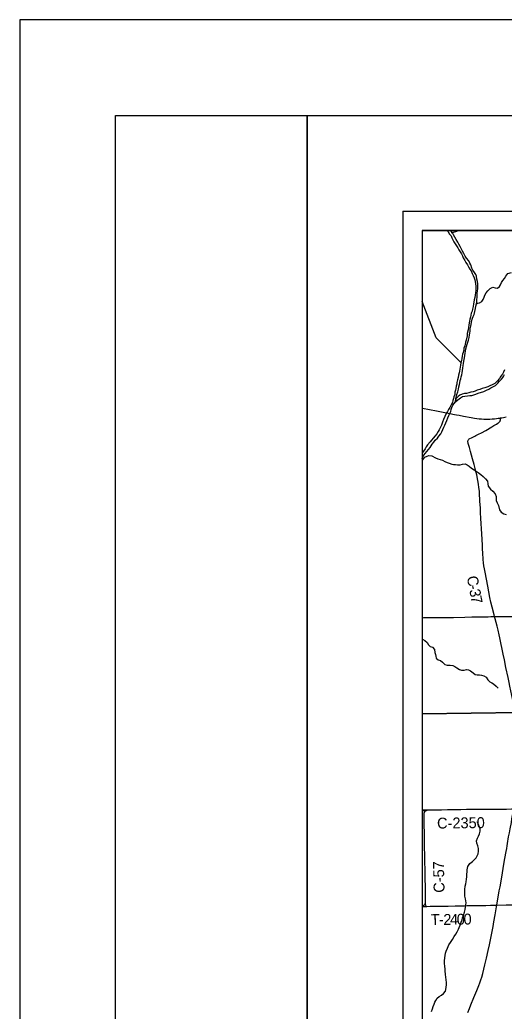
# Model space of a CAD drawing. Extents: x 0 to 34, y 0 to 22.
# Drawn here: x 0 to 2.53, y 16.82 to 22 of the extents above; entities that cross this region are included whole.
import ezdxf

# ---------------------------------------------------------------- set-up
doc = ezdxf.new("R2010")
doc.units = 0
for name, color, linetype in [('Default', 7, 'Continuous'), ('GM_X_County_Road', 7, 'Continuous'), ('GM_X_County_Road_Text', 7, 'Continuous'), ('GM_X_Major_River', 7, 'Continuous'), ('GM_X_Minor_River', 7, 'Continuous'), ('GM_X_State_Route', 7, 'Continuous'), ('GM_X_Township_Road', 7, 'Continuous'), ('GM_X_Township_Road_Text', 7, 'Continuous'), ('SH_Border', 7, 'Continuous'), ('SH_Cut_Line', 7, 'Continuous'), ('SH_Data', 7, 'Continuous')]:
    doc.layers.add(name, color=color, linetype=linetype)

msp = doc.modelspace()

# ---------------------------------------------------------------- linework, layer by layer
at = {"layer": 'Default'}
for points in [[(2.6032, 20.9), (2.1, 20.9), (2.1, 18.375), (2.6118, 18.3803), (2.6161, 18.3799), (2.6204, 18.3797), (2.6263, 18.3795), (2.6292, 18.3794), (2.6281, 18.8843), (2.6224, 19.9515), (2.6032, 20.8721)], [(2.1, 18.375), (2.1, 14.3539), (2.1651, 14.3567), (2.6607, 14.3625), (2.6434, 15.3487), (2.6428, 15.3713), (2.6388, 15.4856), (2.6332, 16.3685), (2.6231, 17.3771), (2.6129, 17.8818), (2.6122, 18.05), (2.6118, 18.3803)]]:
    msp.add_lwpolyline(points, close=True, dxfattribs=at)
at = {"layer": 'GM_X_County_Road'}
for points in [[(2.4785, 18.8823), (2.476, 18.8918), (2.4659, 18.931), (2.4594, 18.9582), (2.4543, 18.9825), (2.443, 19.0404), (2.4287, 19.1136), (2.4252, 19.1319), (2.4228, 19.1473), (2.421, 19.1628), (2.4195, 19.1813), (2.4173, 19.2153), (2.4162, 19.2339), (2.4148, 19.2556), (2.4114, 19.3146), (2.407, 19.3952), (2.4054, 19.4262), (2.4043, 19.448), (2.4024, 19.4851), (2.3998, 19.5284), (2.399, 19.5376), (2.3972, 19.5561), (2.3946, 19.5746), (2.3915, 19.5929), (2.3897, 19.6021), (2.3872, 19.6141), (2.3852, 19.6231), (2.3808, 19.6407), (2.3793, 19.6466), (2.377, 19.6556), (2.3714, 19.6766), (2.3631, 19.7065), (2.3527, 19.7455), (2.347, 19.7663), (2.3427, 19.7812), (2.341, 19.7873), (2.3403, 19.7903), (2.3397, 19.7936), (2.3394, 19.7969), (2.3397, 19.8005), (2.3404, 19.8034), (2.342, 19.8063), (2.3442, 19.8086), (2.3465, 19.8107), (2.3493, 19.8124), (2.358, 19.8164), (2.3747, 19.8246), (2.3802, 19.8275), (2.3941, 19.8344), (2.4105, 19.8431), (2.4322, 19.8552), (2.4644, 19.8736), (2.4751, 19.8798), (2.4858, 19.8862), (2.4885, 19.8877), (2.4963, 19.8927), (2.4988, 19.8945), (2.5011, 19.8965), (2.5033, 19.8985), (2.5052, 19.9007), (2.5069, 19.9032), (2.5081, 19.9058), (2.5089, 19.9086), (2.5092, 19.9115), (2.51, 19.92)], [(2.612, 18.3797), (2.605, 18.3816), (2.6008, 18.3837), (2.5961, 18.3866), (2.5918, 18.3897), (2.5882, 18.3934), (2.5844, 18.3998), (2.5827, 18.4047), (2.5816, 18.4095), (2.5789, 18.4216), (2.5635, 18.4945), (2.5585, 18.5189), (2.5548, 18.5371), (2.5491, 18.5645), (2.5379, 18.6161), (2.5297, 18.6557), (2.5233, 18.6861), (2.5056, 18.7712), (2.5023, 18.7864), (2.4967, 18.8106), (2.4913, 18.8316), (2.4814, 18.8708), (2.4785, 18.8823)], [(2.113, 17.8603), (2.1148, 17.8631), (2.1167, 17.865), (2.1199, 17.8677), (2.1232, 17.8697), (2.1271, 17.8713), (2.1302, 17.8721), (2.1338, 17.8727)], [(2.1338, 17.8727), (2.143, 17.873), (2.1679, 17.8731), (2.2021, 17.8734), (2.2332, 17.8737), (2.2706, 17.8742), (2.3017, 17.8749), (2.3328, 17.8752), (2.3483, 17.8753), (2.3639, 17.8754), (2.3825, 17.8755), (2.4074, 17.8755), (2.4447, 17.8757), (2.4883, 17.8761), (2.5256, 17.8767), (2.5411, 17.8769), (2.5661, 17.877), (2.5714, 17.8773), (2.5741, 17.8774), (2.5755, 17.8776), (2.5786, 17.8784), (2.5792, 17.8787)], [(2.4906, 17.3748), (2.5032, 17.4493), (2.507, 17.4707), (2.5177, 17.5319), (2.5258, 17.5778), (2.5327, 17.6176), (2.5393, 17.6543), (2.5418, 17.6697), (2.5441, 17.685), (2.546, 17.6973), (2.5521, 17.7309), (2.5561, 17.7522), (2.5601, 17.7736), (2.5662, 17.8072), (2.5695, 17.8255), (2.5792, 17.8787)], [(2.1156, 17.3812), (2.1165, 17.3836), (2.1171, 17.3856), (2.1176, 17.3877), (2.1179, 17.3899), (2.1182, 17.3935), (2.1187, 17.4028), (2.1187, 17.4277), (2.1178, 17.4682), (2.1168, 17.5149), (2.116, 17.5616), (2.1152, 17.599), (2.1145, 17.627), (2.1133, 17.6862), (2.1125, 17.736), (2.1105, 17.8077), (2.1102, 17.8214), (2.1105, 17.8354), (2.1105, 17.8414), (2.1107, 17.8482), (2.111, 17.8518), (2.1116, 17.8556), (2.113, 17.8603)], [(2.1, 17.3692), (2.1009, 17.3694), (2.1042, 17.3705), (2.1075, 17.3721), (2.1099, 17.3737), (2.1125, 17.3761), (2.1143, 17.3787), (2.1156, 17.3812)], [(2.3387, 16.8142), (2.347, 16.8343), (2.3551, 16.8545), (2.37, 16.8919), (2.3858, 16.9289), (2.3965, 16.9546), (2.4022, 16.9691), (2.4073, 16.9838), (2.4119, 16.9987), (2.4168, 17.0167), (2.4277, 17.062), (2.4362, 17.0983), (2.4451, 17.1377), (2.4516, 17.1681), (2.4623, 17.2199), (2.4708, 17.2625), (2.4753, 17.287), (2.4817, 17.3237), (2.4892, 17.3666), (2.4906, 17.3748)]]:
    msp.add_lwpolyline(points, dxfattribs=at)
at = {"layer": 'GM_X_Major_River'}
for points in [[(2.2303, 20.9), (2.236, 20.892), (2.2439, 20.8809), (2.2511, 20.8714), (2.2548, 20.8604), (2.2605, 20.8505)], [(2.3133, 20.1805), (2.3151, 20.1946), (2.3163, 20.2048), (2.3177, 20.217), (2.3207, 20.2333), (2.3226, 20.2466), (2.3244, 20.258), (2.3263, 20.2697), (2.3293, 20.2807), (2.3323, 20.294), (2.3357, 20.3047), (2.3395, 20.3157), (2.3425, 20.3267), (2.3454, 20.34), (2.3484, 20.3536), (2.3496, 20.3631), (2.3503, 20.373), (2.3518, 20.3851), (2.3548, 20.3992), (2.3562, 20.4087), (2.3589, 20.4204), (2.3622, 20.436), (2.3667, 20.4493), (2.3713, 20.4603), (2.3754, 20.4759), (2.3784, 20.4911), (2.3814, 20.5036), (2.3836, 20.5154), (2.3855, 20.5256), (2.3866, 20.5389), (2.3869, 20.5499), (2.3873, 20.5617), (2.388, 20.5715), (2.3895, 20.5837), (2.391, 20.5954), (2.3917, 20.608), (2.3905, 20.6209), (2.389, 20.6322), (2.3867, 20.6459), (2.3836, 20.6599), (2.3801, 20.6694), (2.3737, 20.68), (2.3649, 20.6925), (2.3599, 20.7023), (2.3538, 20.7194), (2.35, 20.7292), (2.3435, 20.7417), (2.3317, 20.7554), (2.3249, 20.7656), (2.3176, 20.7785), (2.3111, 20.791), (2.3058, 20.8023), (2.2985, 20.8164), (2.2924, 20.8281), (2.286, 20.8379), (2.2787, 20.852), (2.2711, 20.8645), (2.2646, 20.8762), (2.2585, 20.8864), (2.252, 20.8966), (2.2504, 20.9)], [(2.2605, 20.8505), (2.2657, 20.8406), (2.2733, 20.8299), (2.2796, 20.8192), (2.2864, 20.8086), (2.2924, 20.7983), (2.2981, 20.7876), (2.3052, 20.7766), (2.3108, 20.7671), (2.3153, 20.7572), (2.3232, 20.7427), (2.3288, 20.7317), (2.3364, 20.7206), (2.342, 20.7092), (2.3495, 20.6978), (2.3567, 20.6879), (2.3615, 20.6742), (2.3672, 20.6635), (2.372, 20.6529), (2.3746, 20.6422), (2.378, 20.6323), (2.3794, 20.6206), (2.3801, 20.608), (2.3805, 20.5978), (2.38, 20.5853), (2.3784, 20.5747), (2.3776, 20.5614), (2.3753, 20.5489), (2.3722, 20.5371), (2.3706, 20.5254), (2.3686, 20.5159), (2.3667, 20.5026), (2.3632, 20.4882), (2.3609, 20.4787), (2.357, 20.4678), (2.3551, 20.4572), (2.3524, 20.4465), (2.35, 20.4367), (2.3481, 20.4265), (2.3458, 20.4166), (2.3442, 20.4048), (2.3418, 20.392), (2.3403, 20.3806), (2.3348, 20.3605), (2.3348, 20.3491), (2.3309, 20.3271), (2.3266, 20.3158), (2.3254, 20.3059), (2.3231, 20.2961), (2.3185, 20.2843), (2.3181, 20.2748), (2.3146, 20.2627), (2.3119, 20.2525), (2.3099, 20.2422), (2.308, 20.2309), (2.3057, 20.2195), (2.3022, 20.2074), (2.3002, 20.1964), (2.2986, 20.1846), (2.2967, 20.1748), (2.2951, 20.1645), (2.2932, 20.1551), (2.2897, 20.1437), (2.2877, 20.1312), (2.2846, 20.1187), (2.2823, 20.1054), (2.2811, 20.0959), (2.2773, 20.0853), (2.2757, 20.0743), (2.2753, 20.0645), (2.2714, 20.0542), (2.2714, 20.0429), (2.266, 20.0311), (2.2644, 20.0209), (2.2613, 20.011), (2.2586, 20.0009)], [(2.2762, 20.0203), (2.2811, 20.0423), (2.2867, 20.056), (2.2901, 20.0697), (2.2927, 20.0822), (2.2946, 20.0943), (2.2968, 20.1042), (2.2994, 20.1148), (2.3021, 20.1243), (2.3047, 20.135), (2.3069, 20.1445), (2.3092, 20.1551), (2.3114, 20.168), (2.3133, 20.1805)], [(2.1, 19.7082), (2.1063, 19.7203), (2.1168, 19.7347), (2.1244, 19.7443), (2.133, 19.7549), (2.1417, 19.7663), (2.1534, 19.7831), (2.1613, 19.7941), (2.1692, 19.8036), (2.1802, 19.8147), (2.1881, 19.825), (2.1971, 19.8364), (2.2035, 19.8474), (2.2088, 19.8596), (2.214, 19.8713), (2.2197, 19.8831), (2.2242, 19.8953), (2.229, 19.9063), (2.235, 19.9208), (2.2399, 19.9322), (2.2448, 19.9424), (2.2497, 19.9531), (2.2527, 19.9633), (2.2553, 19.974), (2.2605, 19.9869), (2.2744, 20.0044)], [(2.2586, 20.0009), (2.2526, 19.9884), (2.2443, 19.9747), (2.2379, 19.9633), (2.2322, 19.9534), (2.2236, 19.9405), (2.2183, 19.9275), (2.2123, 19.9127), (2.2071, 19.8986), (2.2011, 19.8831), (2.1955, 19.8717), (2.1887, 19.8583), (2.1834, 19.8485), (2.1766, 19.8374), (2.1691, 19.8272), (2.1585, 19.8146), (2.1499, 19.8047), (2.1416, 19.7952), (2.1291, 19.7788), (2.122, 19.7689), (2.1167, 19.759), (2.1077, 19.7465), (2.1, 19.7339)], [(2.2744, 20.0044), (2.2762, 20.0203)]]:
    msp.add_lwpolyline(points, dxfattribs=at)
at = {"layer": 'GM_X_Minor_River'}
for points in [[(2.2564, 20.8897), (2.254, 20.8875), (2.2642, 20.8902), (2.2771, 20.8948), (2.2909, 20.9)], [(2.3836, 20.5154), (2.3901, 20.5192), (2.3999, 20.5207), (2.4128, 20.528), (2.4188, 20.5382), (2.4241, 20.5512), (2.4275, 20.5622), (2.4347, 20.5743), (2.4434, 20.5846), (2.4555, 20.5964), (2.4695, 20.6036), (2.4812, 20.5999), (2.4945, 20.5984), (2.5047, 20.6064), (2.5096, 20.6163), (2.5149, 20.6277), (2.5221, 20.6376), (2.5308, 20.6494), (2.5376, 20.6615), (2.5478, 20.6752), (2.567, 20.6805)], [(2.3027, 20.2091), (2.174, 20.3379), (2.1, 20.5276)], [(2.531, 20.1721), (2.5243, 20.1584), (2.5194, 20.1481), (2.5118, 20.1375), (2.505, 20.1265), (2.4925, 20.1116), (2.4797, 20.1006), (2.4664, 20.0933), (2.4531, 20.0872), (2.4429, 20.0827), (2.4274, 20.0773), (2.4137, 20.0735), (2.4009, 20.0685), (2.3884, 20.0643), (2.3766, 20.0597), (2.3671, 20.0562), (2.3539, 20.0547), (2.344, 20.0516), (2.3311, 20.0478), (2.3216, 20.0478), (2.3099, 20.0447), (2.2978, 20.0393), (2.2879, 20.0325), (2.2762, 20.0203)], [(2.2744, 20.0044), (2.2865, 20.0154), (2.3008, 20.0257), (2.3114, 20.0322), (2.3224, 20.0345), (2.3372, 20.0357), (2.3494, 20.0365), (2.36, 20.0376), (2.3698, 20.0407), (2.3801, 20.0441), (2.3933, 20.0491), (2.4217, 20.0587), (2.4358, 20.0656), (2.4483, 20.0709), (2.4589, 20.0766), (2.4725, 20.0846), (2.4827, 20.09), (2.4963, 20.1018), (2.5047, 20.1113), (2.516, 20.1246), (2.5243, 20.136), (2.5311, 20.1474)], [(2.2762, 20.0203), (2.2744, 20.0044)], [(2.1, 19.7015), (2.1041, 19.702), (2.115, 19.7154), (2.126, 19.7207), (2.1358, 19.7246), (2.1502, 19.7223), (2.1707, 19.7118), (2.1821, 19.7069), (2.195, 19.7035), (2.206, 19.7002), (2.2189, 19.693), (2.2307, 19.6866), (2.2417, 19.6832), (2.2554, 19.6787), (2.2649, 19.6776), (2.2747, 19.6761), (2.2857, 19.6754), (2.2986, 19.6758), (2.3115, 19.6785), (2.3255, 19.6794), (2.3357, 19.6748), (2.346, 19.6673), (2.3586, 19.6578), (2.3715, 19.6492), (2.3825, 19.6424), (2.3924, 19.6348), (2.4061, 19.6239), (2.4186, 19.6137), (2.4304, 19.6019), (2.4411, 19.5898), (2.4434, 19.5766), (2.4454, 19.5633), (2.4568, 19.5482), (2.469, 19.538), (2.4815, 19.5232), (2.4865, 19.5103), (2.4877, 19.5005), (2.4877, 19.4887), (2.492, 19.4758), (2.4988, 19.4633), (2.5042, 19.4398), (2.5138, 19.4281), (2.5267, 19.4194), (2.5396, 19.4153)], [(2.1, 18.7665), (2.1019, 18.765), (2.1145, 18.7575), (2.1259, 18.7469), (2.1328, 18.734), (2.1423, 18.7261), (2.154, 18.7227), (2.1651, 18.7102), (2.1667, 18.6954), (2.1694, 18.6844), (2.1713, 18.6746), (2.1732, 18.6651), (2.1839, 18.6568), (2.1968, 18.6523), (2.2067, 18.6447), (2.2181, 18.6322), (2.231, 18.6281), (2.2469, 18.6286), (2.2609, 18.6263), (2.2708, 18.6214), (2.2811, 18.615), (2.2959, 18.606), (2.3061, 18.6018), (2.3205, 18.603), (2.3315, 18.605), (2.3418, 18.6046), (2.3524, 18.599), (2.3661, 18.5876), (2.3775, 18.5801), (2.387, 18.5771), (2.3999, 18.5771), (2.4097, 18.5764), (2.423, 18.5723), (2.434, 18.5655), (2.4439, 18.5526), (2.4542, 18.5417), (2.4641, 18.536), (2.4736, 18.5307), (2.4861, 18.5194), (2.4972, 18.5077)], [(2.363, 17.602), (2.3826, 17.6218), (2.3883, 17.6314), (2.392, 17.6431), (2.3954, 17.656), (2.3949, 17.6712), (2.3919, 17.6845), (2.3861, 17.6985), (2.3845, 17.7114), (2.3886, 17.7247), (2.395, 17.7354), (2.3995, 17.7464), (2.4029, 17.7616), (2.4029, 17.7726), (2.3998, 17.7828), (2.3944, 17.7965), (2.3879, 17.8097)], [(2.1484, 16.8191), (2.1536, 16.8331), (2.1577, 16.8445), (2.1626, 16.8574), (2.1667, 16.8673), (2.1716, 16.8772), (2.1784, 16.8879), (2.1886, 16.8978), (2.2015, 16.9043), (2.2113, 16.9123), (2.2218, 16.9245), (2.2241, 16.9343), (2.2263, 16.9461), (2.2278, 16.9586), (2.2277, 16.9689), (2.2261, 16.986), (2.2246, 16.997), (2.2222, 17.0136), (2.221, 17.03), (2.2202, 17.0398), (2.2186, 17.0561), (2.2174, 17.0702), (2.217, 17.0831), (2.2181, 17.099), (2.2199, 17.1112), (2.2225, 17.1241), (2.2259, 17.134), (2.2319, 17.1499), (2.2402, 17.167), (2.2488, 17.1796), (2.259, 17.1959), (2.2676, 17.2112), (2.2759, 17.2226), (2.2831, 17.2355), (2.2895, 17.2484), (2.2936, 17.2579), (2.2985, 17.2701), (2.3045, 17.2864), (2.309, 17.2986), (2.3112, 17.3089), (2.3157, 17.321), (2.3209, 17.3374), (2.3254, 17.351), (2.3273, 17.3632), (2.3291, 17.3761), (2.3294, 17.3863), (2.3279, 17.3973), (2.3263, 17.4068), (2.324, 17.4216), (2.3232, 17.4319), (2.3224, 17.4474), (2.3227, 17.4569), (2.3253, 17.4736), (2.3279, 17.4854), (2.3301, 17.4964), (2.3323, 17.5101), (2.3334, 17.5226), (2.3345, 17.5367), (2.3352, 17.548), (2.3359, 17.5598), (2.3389, 17.5758), (2.3502, 17.5914), (2.363, 17.602)]]:
    msp.add_lwpolyline(points, dxfattribs=at)
at = {"layer": 'GM_X_State_Route'}
msp.add_lwpolyline([(2.1, 19.9721), (2.1024, 19.9716), (2.1757, 19.9576), (2.2275, 19.9473), (2.2458, 19.9437), (2.2701, 19.9388), (2.2792, 19.937), (2.2945, 19.9341), (2.3158, 19.93), (2.3555, 19.9225), (2.3738, 19.9193), (2.3861, 19.9175), (2.3984, 19.9161), (2.4108, 19.9151), (2.4231, 19.9145), (2.4355, 19.9142), (2.4448, 19.9142), (2.4541, 19.9145), (2.4665, 19.9151), (2.4788, 19.9161), (2.4881, 19.917), (2.4973, 19.9181), (2.5065, 19.9195), (2.51, 19.92), (2.5157, 19.921), (2.5248, 19.9226), (2.5399, 19.926)], dxfattribs=at)
at = {"layer": 'GM_X_Township_Road'}
msp.add_line((2.1, 17.3684), (2.123, 17.3683), dxfattribs=at)
for points in [[(2.1, 18.8764), (2.1077, 18.8766), (2.121, 18.8767), (2.1292, 18.8768), (2.1464, 18.8769), (2.1639, 18.8771), (2.1864, 18.8773), (2.2392, 18.8778), (2.264, 18.8783), (2.3228, 18.8793), (2.36, 18.8802), (2.3817, 18.8807), (2.4003, 18.8811), (2.4221, 18.8814), (2.4443, 18.8815), (2.4593, 18.8818), (2.4785, 18.8823)], [(2.4785, 18.8823), (2.4844, 18.8824), (2.498, 18.8826), (2.5319, 18.883), (2.5658, 18.8832), (2.5998, 18.8835), (2.6283, 18.8837)], [(2.1, 17.8723), (2.1021, 17.8724), (2.1028, 17.8724)], [(2.1028, 17.8724), (2.1114, 17.8723), (2.1338, 17.8727)], [(2.1028, 17.8724), (2.1062, 17.8706), (2.1083, 17.8688), (2.1098, 17.867), (2.1112, 17.8649), (2.1122, 17.8629), (2.113, 17.8603)], [(2.1156, 17.3812), (2.1161, 17.3792), (2.1167, 17.3775), (2.1175, 17.3758), (2.1183, 17.3745), (2.1193, 17.3727), (2.1215, 17.3699), (2.123, 17.3683)], [(2.123, 17.3683), (2.1243, 17.3683), (2.1429, 17.3685), (2.1801, 17.3693), (2.208, 17.3698), (2.2358, 17.37), (2.2729, 17.3709), (2.2976, 17.3713), (2.3193, 17.3717), (2.3349, 17.372), (2.3524, 17.3722), (2.377, 17.3726), (2.4036, 17.373), (2.4334, 17.3734), (2.4581, 17.3739), (2.4797, 17.3746), (2.4906, 17.3748)], [(2.4906, 17.3748), (2.4921, 17.3749), (2.5386, 17.3762), (2.5665, 17.3767), (2.6234, 17.3766)]]:
    msp.add_lwpolyline(points, dxfattribs=at)
at = {"layer": 'SH_Border'}
for points in [[(0.5, 21.5), (1.5, 21.5), (1.5, 0.5), (0.5, 0.5)], [(1.5, 21.5), (33.5, 21.5), (33.5, 0.5), (1.5, 0.5)]]:
    msp.add_lwpolyline(points, close=True, dxfattribs=at)
at = {"layer": 'SH_Cut_Line'}
for points in [[(0, 0), (34, 0), (34, 22), (0, 22)], [(2.6032, 20.9), (2.1, 20.9), (2.1, 14.3539), (2.1651, 14.3567), (2.6607, 14.3625), (2.6434, 15.3487), (2.6428, 15.3713), (2.6388, 15.4856), (2.6332, 16.3685), (2.6231, 17.3771), (2.6129, 17.8818), (2.6122, 18.05), (2.6118, 18.3803), (2.6161, 18.3799), (2.6204, 18.3797), (2.6263, 18.3795), (2.6292, 18.3794), (2.6281, 18.8843), (2.6224, 19.9515), (2.6032, 20.8721)]]:
    msp.add_lwpolyline(points, close=True, dxfattribs=at)
at = {"layer": 'SH_Data'}
for p, q in [((2, 21), (9, 21)), ((2, 21), (2, 14)), ((2.1, 20.9), (2.1, 14.1)), ((2.1, 20.9), (8.9, 20.9))]:
    msp.add_line(p, q, dxfattribs=at)

# ---------------------------------------------------------------- texts
at = {"layer": 'GM_X_County_Road_Text'}
for s, height, rotation, p in [('C', 0.0568, 280.8683, (2.3329, 19.0896)), ('3', 0.0568, 280.9654, (2.3462, 19.0208)), ('-', 0.0568, 280.894, (2.3417, 19.0437)), ('7', 0.0568, 281.4361, (2.3529, 18.9859)), ('C-2350', 0.05682, 0.6822, (2.1785, 17.7745)), ('C-57', 0.05682, 91.3653, (2.2177, 17.44))]:
    msp.add_text(s, height=height, rotation=rotation, dxfattribs=at).set_placement(p)
at = {"layer": 'GM_X_Township_Road_Text'}
for s, rotation, p in [('T', 0.7414, (2.1456, 17.2705)), ('2', 0.7539, (2.2114, 17.2713)), ('4', 0.7875, (2.2465, 17.2718)), ('0', 0.9139, (2.2816, 17.2723)), ('0', 1.5524, (2.3173, 17.2728)), ('-', 0.7484, (2.1881, 17.271))]:
    msp.add_text(s, height=0.0568, rotation=rotation, dxfattribs=at).set_placement(p)

doc.saveas('drawing.dxf')
